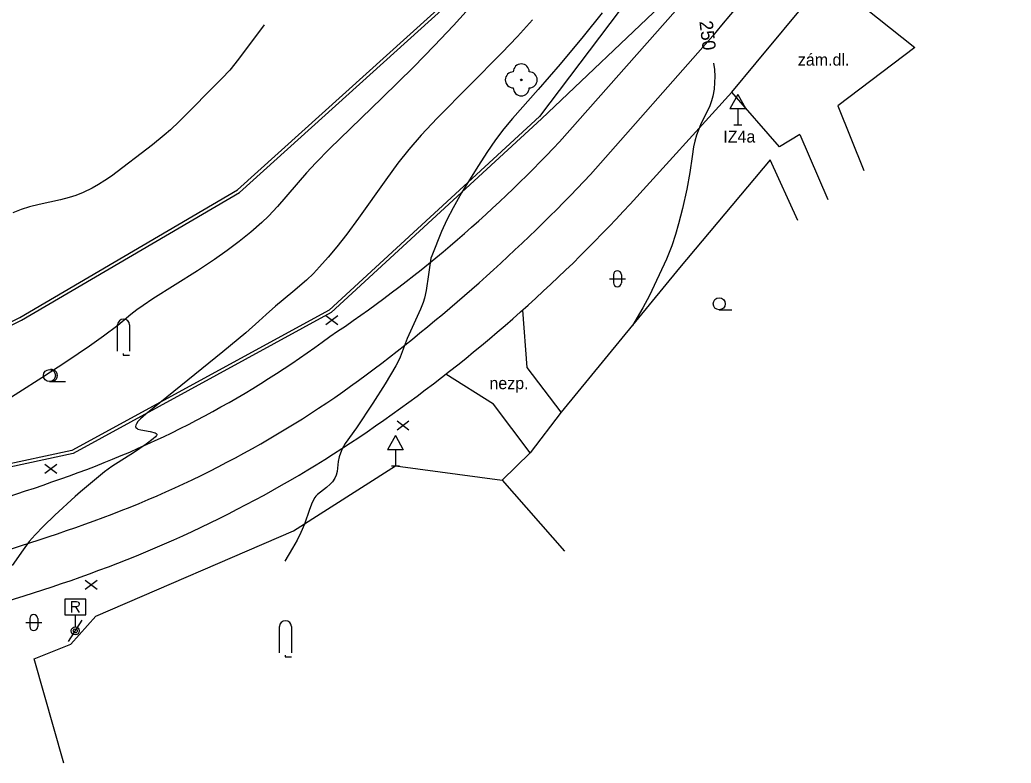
# Model space of a CAD drawing. Extents: x -593772 to -592667, y -1183541 to -1183371.
# Drawn here: x -592754.1 to -592692, y -1183533.2 to -1183486.6 of the extents above; entities that cross this region are included whole.
import ezdxf

# ---------------------------------------------------------------- set-up
doc = ezdxf.new("R2010")
doc.units = 0
for name, color, linetype in [('bez obruby', 7, 'Continuous'), ('hlavni vrstevnice', 7, 'Continuous'), ('obruba snizena', 7, 'Continuous'), ('obruba zvysena', 7, 'Continuous'), ('ploty', 7, 'Continuous'), ('popis ploch', 7, 'Continuous'), ('rozhrani ploch', 7, 'Continuous'), ('svisle dopravni znaceni', 7, 'Continuous'), ('terenni hrany', 7, 'Continuous'), ('vodorovne dopravni znaceni', 7, 'Continuous'), ('vrstevnice', 7, 'Continuous'), ('zelen', 7, 'Continuous')]:
    doc.layers.add(name, color=color, linetype=linetype)

msp = doc.modelspace()

# ---------------------------------------------------------------- linework, layer by layer
at = {"layer": 'bez obruby'}
for p, q in [((-592712.97, -1183486.06), (-592720.24, -1183494.25)), ((-592715.82, -1183498.15), (-592709.44, -1183491.15))]:
    msp.add_line(p, q, dxfattribs=at)
for centre, radius, start, end in [((-592780.404, -1183437.835), 82.476, 303.70203, 316.842), ((-592785.66, -1183434.025), 94.814, 305.01281, 317.44306), ((-592771.92, -1183456.267), 62.515, 289.59918, 306.60777), ((-592775.639, -1183449.083), 76.732, 290.23461, 305.33541), ((-592788.634, -1183411.087), 110.686, 280.29638, 289.90486), ((-592783.311, -1183428.474), 98.723, 278.78098, 290.27546)]:
    msp.add_arc(centre, radius, start, end, dxfattribs=at)
at = {"layer": 'hlavni vrstevnice'}
msp.add_lwpolyline([(-592710.598, -1183489.344), (-592710.543, -1183489.734), (-592710.518, -1183490.159), (-592710.526, -1183490.551), (-592710.566, -1183490.963), (-592710.649, -1183491.402), (-592710.726, -1183491.689), (-592710.836, -1183492.001), (-592711.407, -1183493.185), (-592711.524, -1183493.461), (-592711.662, -1183493.848), (-592711.766, -1183494.21), (-592711.845, -1183494.574), (-592711.937, -1183495.167), (-592712.075, -1183496.186), (-592712.265, -1183497.217), (-592712.549, -1183498.431), (-592712.791, -1183499.401), (-592712.971, -1183500.066), (-592713.205, -1183500.758), (-592713.548, -1183501.595), (-592714.308, -1183503.256), (-592714.616, -1183503.884), (-592715.027, -1183504.641), (-592715.682, -1183505.751)], dxfattribs=at)
at = {"layer": 'obruba snizena'}
for p, q in [((-592707.93, -1183489.32), (-592703.42, -1183483.9)), ((-592709.44, -1183491.15), (-592707.93, -1183489.32))]:
    msp.add_line(p, q, dxfattribs=at)
at = {"layer": 'obruba zvysena'}
for p, q in [((-592701.85, -1183485.26), (-592697.99, -1183488.36)), ((-592697.99, -1183488.36), (-592702.81, -1183492)), ((-592706.47, -1183494.57), (-592709.44, -1183491.15)), ((-592702.81, -1183492), (-592701.17, -1183496.06)), ((-592705.19, -1183493.8), (-592706.47, -1183494.57)), ((-592705.19, -1183493.8), (-592703.44, -1183497.87))]:
    msp.add_line(p, q, dxfattribs=at)
at = {"layer": 'ploty'}
for p, q in [((-592707.04, -1183495.39), (-592712.73, -1183502.15)), ((-592705.31, -1183499.19), (-592707.04, -1183495.39)), ((-592712.73, -1183502.15), (-592720.14, -1183511.19)), ((-592720.14, -1183511.19), (-592722.09, -1183513.73)), ((-592722.09, -1183513.73), (-592723.84, -1183515.43))]:
    msp.add_line(p, q, dxfattribs=at)
at = {"layer": 'popis ploch'}
for p, q in [((-592716.87, -1183502.58), (-592716.87, -1183503.08)), ((-592716.37, -1183502.58), (-592716.37, -1183503.08)), ((-592717.12, -1183502.83), (-592716.12, -1183502.83)), ((-592710.24, -1183504.77), (-592709.44, -1183504.77)), ((-592747.93, -1183507.36), (-592747.93, -1183505.71)), ((-592747.18, -1183505.71), (-592747.18, -1183507.36)), ((-592752.2, -1183509.26), (-592751.2, -1183509.26)), ((-592753.68, -1183524.35), (-592752.68, -1183524.35)), ((-592753.43, -1183524.1), (-592753.43, -1183524.6)), ((-592752.93, -1183524.1), (-592752.93, -1183524.6)), ((-592737.79, -1183526.24), (-592737.79, -1183524.59)), ((-592737.04, -1183524.59), (-592737.04, -1183526.24))]:
    msp.add_line(p, q, dxfattribs=at)
for points in [[(-592747.58, -1183507.51), (-592747.58, -1183507.61), (-592747.18, -1183507.61)], [(-592737.44, -1183526.39), (-592737.44, -1183526.49), (-592737.04, -1183526.49)]]:
    msp.add_lwpolyline(points, dxfattribs=at)
for centre in [(-592710.24, -1183504.395), (-592752.199, -1183508.886)]:
    msp.add_circle(centre, 0.375, dxfattribs=at)
for centre, radius, start, end in [((-592716.621, -1183502.58), 0.25, 0, 180), ((-592716.621, -1183503.08), 0.25, 180, 0), ((-592752.074, -1183508.886), 0.375, 260.40593, 99.59407), ((-592753.181, -1183524.1), 0.25, 0, 180), ((-592753.181, -1183524.6), 0.25, 180, 0)]:
    msp.add_arc(centre, radius, start, end, dxfattribs=at)
for centre in [(-592747.555, -1183505.71), (-592737.415, -1183524.59)]:
    msp.add_ellipse(centre, major_axis=(-0.375, 0), ratio=0.935414, start_param=3.141593, end_param=6.283185, dxfattribs=at)
at = {"layer": 'rozhrani ploch'}
for p, q in [((-592722.28, -1183508.38), (-592722.552, -1183504.785)), ((-592724.38, -1183510.67), (-592727.366, -1183508.801)), ((-592720.14, -1183511.19), (-592722.28, -1183508.38)), ((-592722.09, -1183513.73), (-592724.38, -1183510.67))]:
    msp.add_line(p, q, dxfattribs=at)
at = {"layer": 'svisle dopravni znaceni'}
for p, q in [((-592709.07, -1183491.3), (-592709.57, -1183492.2)), ((-592709.07, -1183491.3), (-592708.57, -1183492.2)), ((-592708.57, -1183492.2), (-592709.57, -1183492.2)), ((-592709.07, -1183492.2), (-592709.07, -1183493.2)), ((-592709.32, -1183493.2), (-592708.82, -1183493.2)), ((-592734.885, -1183505.701), (-592734.135, -1183505.139)), ((-592734.885, -1183505.139), (-592734.135, -1183505.701)), ((-592730.425, -1183512.291), (-592729.675, -1183511.728)), ((-592730.425, -1183511.728), (-592729.675, -1183512.291)), ((-592730.53, -1183512.63), (-592731.03, -1183513.53)), ((-592730.53, -1183512.63), (-592730.03, -1183513.53)), ((-592730.03, -1183513.53), (-592731.03, -1183513.53)), ((-592730.53, -1183513.53), (-592730.53, -1183514.53)), ((-592752.485, -1183515.001), (-592751.735, -1183514.438)), ((-592752.485, -1183514.438), (-592751.735, -1183515.001)), ((-592730.78, -1183514.53), (-592730.28, -1183514.53)), ((-592749.955, -1183522.251), (-592749.205, -1183521.688)), ((-592749.955, -1183521.688), (-592749.205, -1183522.251)), ((-592751.01, -1183525.54), (-592750.15, -1183524.2)), ((-592750.58, -1183523.867), (-592750.58, -1183524.617)), ((-592750.58, -1183524.867), (-592750.58, -1183524.867))]:
    msp.add_line(p, q, dxfattribs=at)
msp.add_lwpolyline([(-592751.23, -1183523.867), (-592749.93, -1183523.867), (-592749.93, -1183522.892), (-592751.23, -1183522.892)], close=True, dxfattribs=at)
for points in [[(-592750.809, -1183523.028), (-592750.809, -1183523.727)], [(-592750.809, -1183523.028), (-592750.506, -1183523.028), (-592750.407, -1183523.061), (-592750.374, -1183523.094), (-592750.341, -1183523.16), (-592750.341, -1183523.226), (-592750.374, -1183523.292), (-592750.407, -1183523.325), (-592750.506, -1183523.358), (-592750.809, -1183523.358)], [(-592750.572, -1183523.358), (-592750.341, -1183523.727)]]:
    msp.add_lwpolyline(points, dxfattribs=at)
for radius in [0.25, 0.125]:
    msp.add_circle((-592750.58, -1183524.868), radius, dxfattribs=at)
at = {"layer": 'terenni hrany'}
for p, q in [((-592740.42, -1183497.27), (-592726.34, -1183484.57)), ((-592713.54, -1183485.37), (-592721.37, -1183492.81)), ((-592721.37, -1183492.81), (-592734.56, -1183504.95)), ((-592754.05, -1183505.25), (-592740.42, -1183497.27)), ((-592734.56, -1183504.95), (-592750.72, -1183513.77)), ((-592770.7, -1183513.58), (-592754.05, -1183505.25)), ((-592750.72, -1183513.77), (-592768.74, -1183517.64))]:
    msp.add_line(p, q, dxfattribs=at)
at = {"layer": 'vodorovne dopravni znaceni'}
msp.add_line((-592710.65, -1183487.63), (-592718.3, -1183496.3), dxfattribs=at)
for centre, radius, start, end in [((-592458.669, -1183696.357), 327.203, 135.4759, 140.36347), ((-592797.295, -1183421.907), 108.51, 306.44106, 316.71831), ((-592772.061, -1183455.257), 66.694, 289.33419, 306.0202), ((-592785.787, -1183418.791), 105.652, 279.27956, 289.81054)]:
    msp.add_arc(centre, radius, start, end, dxfattribs=at)
at = {"layer": 'vrstevnice'}
for points in [[(-592725.695, -1183485.665), (-592726.892, -1183486.98), (-592728.098, -1183488.253), (-592729.376, -1183489.553), (-592731.346, -1183491.495), (-592734.646, -1183494.701), (-592735.504, -1183495.565), (-592736.103, -1183496.202), (-592737.917, -1183498.299), (-592738.479, -1183498.904), (-592738.895, -1183499.304), (-592739.592, -1183499.912), (-592740.321, -1183500.502), (-592741.056, -1183501.056), (-592741.861, -1183501.624), (-592742.915, -1183502.324), (-592745.719, -1183504.091), (-592746.332, -1183504.501), (-592746.726, -1183504.783), (-592747.095, -1183505.074), (-592747.922, -1183505.755), (-592748.813, -1183506.425), (-592749.688, -1183507.044), (-592751.118, -1183508.008), (-592752.686, -1183509.026), (-592755.579, -1183510.872)], [(-592717.566, -1183486.178), (-592718.764, -1183487.66), (-592720.213, -1183489.396), (-592721.586, -1183490.99), (-592723.195, -1183492.796), (-592723.731, -1183493.442), (-592724.256, -1183494.139), (-592724.805, -1183494.931), (-592725.326, -1183495.729), (-592725.987, -1183496.798), (-592726.377, -1183497.457), (-592726.905, -1183498.389), (-592727.299, -1183499.15), (-592727.63, -1183499.866), (-592728.252, -1183501.389), (-592728.3, -1183501.541), (-592728.463, -1183502.553), (-592728.607, -1183503.564), (-592728.707, -1183504.045), (-592728.788, -1183504.321), (-592728.944, -1183504.725), (-592729.783, -1183506.577), (-592730.226, -1183507.729), (-592730.372, -1183508.047), (-592730.497, -1183508.275), (-592731.161, -1183509.403), (-592731.937, -1183510.606), (-592732.964, -1183512.15), (-592733.664, -1183513.139), (-592733.858, -1183513.483), (-592733.97, -1183513.742), (-592734.048, -1183513.98), (-592734.109, -1183514.276), (-592734.184, -1183514.887), (-592734.242, -1183515.126), (-592734.319, -1183515.314), (-592734.468, -1183515.547), (-592734.605, -1183515.694), (-592734.837, -1183515.896), (-592735.397, -1183516.324), (-592735.521, -1183516.441), (-592735.584, -1183516.529), (-592735.737, -1183516.841), (-592735.907, -1183517.277), (-592736.23, -1183518.195), (-592736.446, -1183518.717), (-592736.672, -1183519.182), (-592736.964, -1183519.703), (-592737.462, -1183520.499)], [(-592721.932, -1183486.617), (-592722.88, -1183487.662), (-592723.86, -1183488.689), (-592727.903, -1183492.777), (-592728.915, -1183493.847), (-592729.689, -1183494.728), (-592730.364, -1183495.583), (-592731.131, -1183496.631), (-592732.831, -1183499.033), (-592733.568, -1183500.029), (-592734.19, -1183500.825), (-592734.736, -1183501.482), (-592735.272, -1183502.088), (-592735.665, -1183502.5), (-592736.086, -1183502.907), (-592736.956, -1183503.649), (-592738.045, -1183504.543), (-592738.63, -1183505.076), (-592739.074, -1183505.492), (-592739.893, -1183506.21), (-592741.331, -1183507.408), (-592746.168, -1183511.307), (-592746.496, -1183511.598), (-592746.654, -1183511.766), (-592746.754, -1183511.912), (-592746.792, -1183512.003), (-592746.799, -1183512.074), (-592746.78, -1183512.138), (-592746.733, -1183512.19), (-592746.654, -1183512.237), (-592746.475, -1183512.289), (-592745.894, -1183512.396), (-592745.577, -1183512.477), (-592745.504, -1183512.515), (-592745.475, -1183512.548), (-592745.467, -1183512.59), (-592745.484, -1183512.64), (-592745.556, -1183512.734), (-592745.701, -1183512.855), (-592746.147, -1183513.186), (-592746.878, -1183513.677), (-592748.285, -1183514.581), (-592748.751, -1183514.912), (-592750.244, -1183516.16), (-592750.591, -1183516.465), (-592751.858, -1183517.623), (-592752.567, -1183518.306), (-592753.095, -1183518.854), (-592753.467, -1183519.281), (-592753.855, -1183519.794), (-592754.539, -1183520.786)], [(-592738.746, -1183486.926), (-592740.363, -1183489.092), (-592740.907, -1183489.765), (-592741.396, -1183490.303), (-592744.066, -1183492.977), (-592744.623, -1183493.507), (-592745.006, -1183493.843), (-592745.739, -1183494.437), (-592748.318, -1183496.398), (-592748.732, -1183496.686), (-592749.134, -1183496.939), (-592749.527, -1183497.161), (-592750.079, -1183497.428), (-592750.549, -1183497.615), (-592750.97, -1183497.752), (-592751.514, -1183497.893), (-592752.853, -1183498.179), (-592753.449, -1183498.332), (-592753.963, -1183498.498), (-592754.491, -1183498.703)]]:
    msp.add_lwpolyline(points, dxfattribs=at)
at = {"layer": 'zelen'}
for p, q in [((-592740.301, -1183497.432), (-592726.204, -1183484.717)), ((-592715.63, -1183484.91), (-592721.508, -1183492.665)), ((-592721.508, -1183492.665), (-592734.677, -1183504.786)), ((-592753.955, -1183505.426), (-592740.301, -1183497.432)), ((-592734.677, -1183504.786), (-592750.79, -1183513.581)), ((-592770.633, -1183513.77), (-592753.955, -1183505.426)), ((-592750.79, -1183513.581), (-592768.772, -1183517.442)), ((-592736.92, -1183518.61), (-592730.53, -1183514.53)), ((-592730.53, -1183514.53), (-592723.84, -1183515.43)), ((-592723.84, -1183515.43), (-592719.94, -1183519.89)), ((-592749.3, -1183523.95), (-592736.92, -1183518.61)), ((-592750.87, -1183525.7), (-592749.3, -1183523.95)), ((-592753.15, -1183526.62), (-592750.87, -1183525.7)), ((-592751.29, -1183533.15), (-592753.15, -1183526.62))]:
    msp.add_line(p, q, dxfattribs=at)
msp.add_circle((-592722.64, -1183490.38), 0.05, dxfattribs=at)
for centre, start, end in [((-592722.64, -1183489.88), 0, 180), ((-592723.14, -1183490.38), 90, 270), ((-592722.14, -1183490.38), 270, 90), ((-592722.64, -1183490.88), 180, 0)]:
    msp.add_arc(centre, 0.5, start, end, dxfattribs=at)

# ---------------------------------------------------------------- texts
at = {"layer": 'hlavni vrstevnice'}
msp.add_text('250', height=0.8351, rotation=276.78807, dxfattribs=at).set_placement((-592711.487, -1183486.721))
at = {"layer": 'popis ploch'}
for s, p in [('zám.dl.', (-592705.315, -1183489.49)), ('nezp.', (-592724.637, -1183509.74))]:
    msp.add_text(s, height=0.75, dxfattribs=at).set_placement(p)
at = {"layer": 'svisle dopravni znaceni'}
msp.add_text('IZ4a', height=0.75, dxfattribs=at).set_placement((-592709.983, -1183494.3))

doc.saveas('drawing.dxf')
